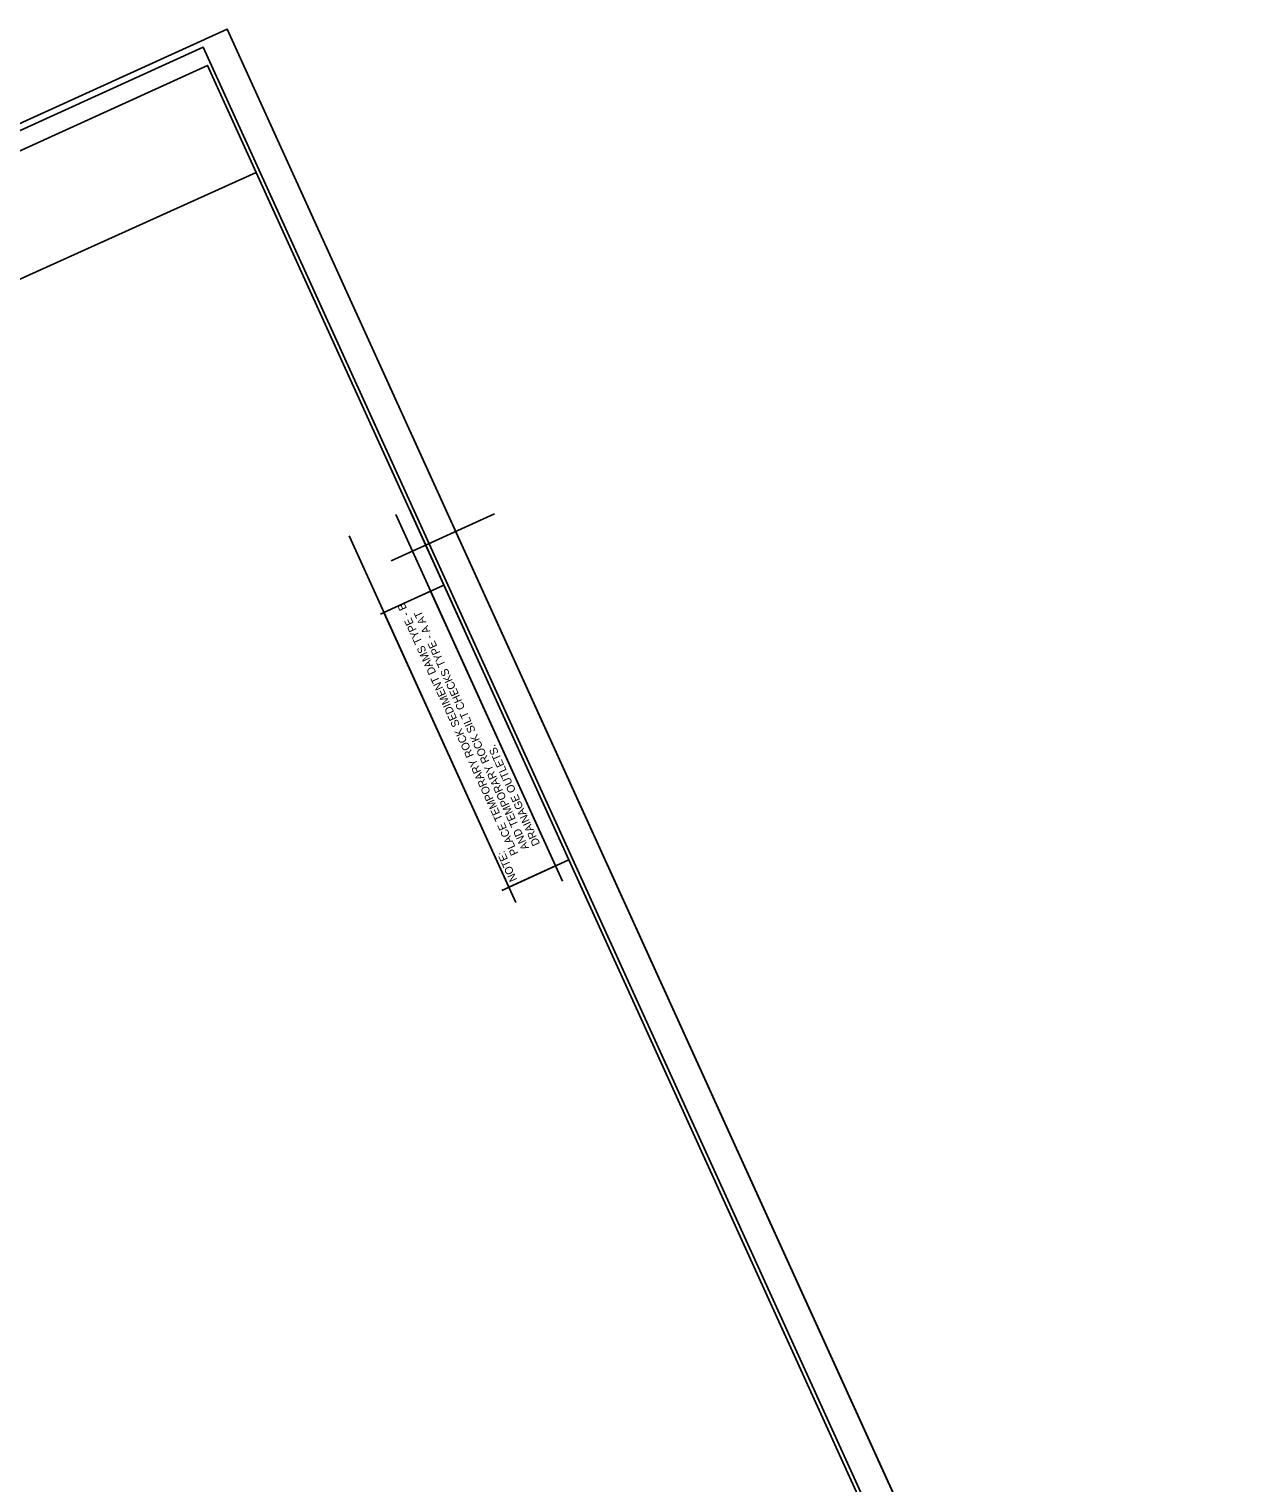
# Model space of a CAD drawing. Extents: x 2097293 to 2098987, y 683915 to 685901.
# Drawn here: x 2098154 to 2098987, y 684908 to 685901 of the extents above; entities that cross this region are included whole.
import ezdxf

# ---------------------------------------------------------------- set-up
doc = ezdxf.new("R2010")
doc.units = 0
for name, color, linetype in [('Construction Sheet Number Note CG CELL', 7, 'Continuous'), ('Scratch_Level_6', 7, 'Continuous'), ('Sheet Cutting Line CELL', 7, 'Continuous'), ('Sheet Layout Plan Border', 7, 'Continuous'), ('Sheet Plan CELL', 7, 'Continuous'), ('Sheet Plot Border Inside CELL', 7, 'Continuous'), ('Sheet Plot Border Outside CELL', 7, 'Continuous')]:
    doc.layers.add(name, color=color, linetype=linetype)

msp = doc.modelspace()

# ---------------------------------------------------------------- linework, layer by layer
at = {"layer": 'Construction Sheet Number Note CG CELL'}
msp.add_lwpolyline([(2098481.82, 685314.86), (2098396.47, 685502.42), (2098428.41, 685516.96), (2098513.77, 685329.4)], close=True, dxfattribs=at)
at = {"layer": 'Scratch_Level_6'}
for p, q in [((2098255.83, 685866.9), (2098276, 685876.08)), ((2098451.11, 685491.25), (2098413.71, 685573.45)), ((2098401.37, 685537.61), (2098472.01, 685569.76)), ((2098518.58, 685318.85), (2098404.61, 685569.31)), ((2098486.62, 685304.31), (2098372.65, 685554.77)), ((2098417.35, 685511.92), (2098437.53, 685521.1)), ((2098401.5, 685504.71), (2098394.1, 685501.34)), ((2098476.94, 685312.64), (2098522.88, 685333.54))]:
    msp.add_line(p, q, dxfattribs=at)
at = {"layer": 'Sheet Cutting Line CELL'}
msp.add_line((2098986.71, 684368.56), (2098289.45, 685900.88), dxfattribs=at)
at = {"layer": 'Sheet Layout Plan Border'}
for points in [[(2098897.26, 684510.8), (2097941.56, 684075.89), (2097486.05, 685076.91), (2097476.37, 685098.19), (2097403.15, 685259.11), (2097618.23, 685357), (2097567.61, 685468.23), (2098309.25, 685803.01)], [(2098897.26, 684510.8), (2097941.56, 684075.89), (2097486.05, 685076.91), (2097476.38, 685098.16), (2097403.15, 685259.11), (2097618.23, 685357), (2097567.61, 685468.23), (2098309.25, 685803.01)]]:
    msp.add_lwpolyline(points, close=True, dxfattribs=at)
at = {"layer": 'Sheet Plan CELL'}
for points in [[(2097320.28, 685441.22), (2097941.56, 684075.89), (2098897.27, 684510.77), (2098276, 685876.08)], [(2098897.27, 684510.77), (2097941.59, 684075.88), (2097403.14, 685259.11), (2097539.72, 685321.27), (2097456.88, 685503.35), (2098276, 685876.08)]]:
    msp.add_lwpolyline(points, close=True, dxfattribs=at)
at = {"layer": 'Sheet Plot Border Inside CELL'}
msp.add_lwpolyline([(2098963.13, 684372.11), (2098273.1, 685888.48), (2097312.85, 685451.54), (2098002.87, 683935.16)], close=True, dxfattribs=at)
at = {"layer": 'Sheet Plot Border Outside CELL'}
msp.add_lwpolyline([(2098986.71, 684368.56), (2098289.45, 685900.88), (2097292.78, 685447.36), (2097990.05, 683915.04)], close=True, dxfattribs=at)

# ---------------------------------------------------------------- texts
at = {"layer": 'Construction Sheet Number Note CG CELL'}
for s, p in [('PLACE TEMPORARY ROCK SEDIMENT DAMS TYPE - B', (2098488.45, 685337.93)), ('AND TEMPORARY ROCK SILT CHECKS TYPE - A AT', (2098495.67, 685341.63)), ('DRAINAGE OUTLETS.', (2098503.27, 685344.47)), ('NOTE:', (2098487.69, 685320.05))]:
    msp.add_text(s, height=5.4, rotation=114.47171, dxfattribs=at).set_placement(p)

doc.saveas('drawing.dxf')
